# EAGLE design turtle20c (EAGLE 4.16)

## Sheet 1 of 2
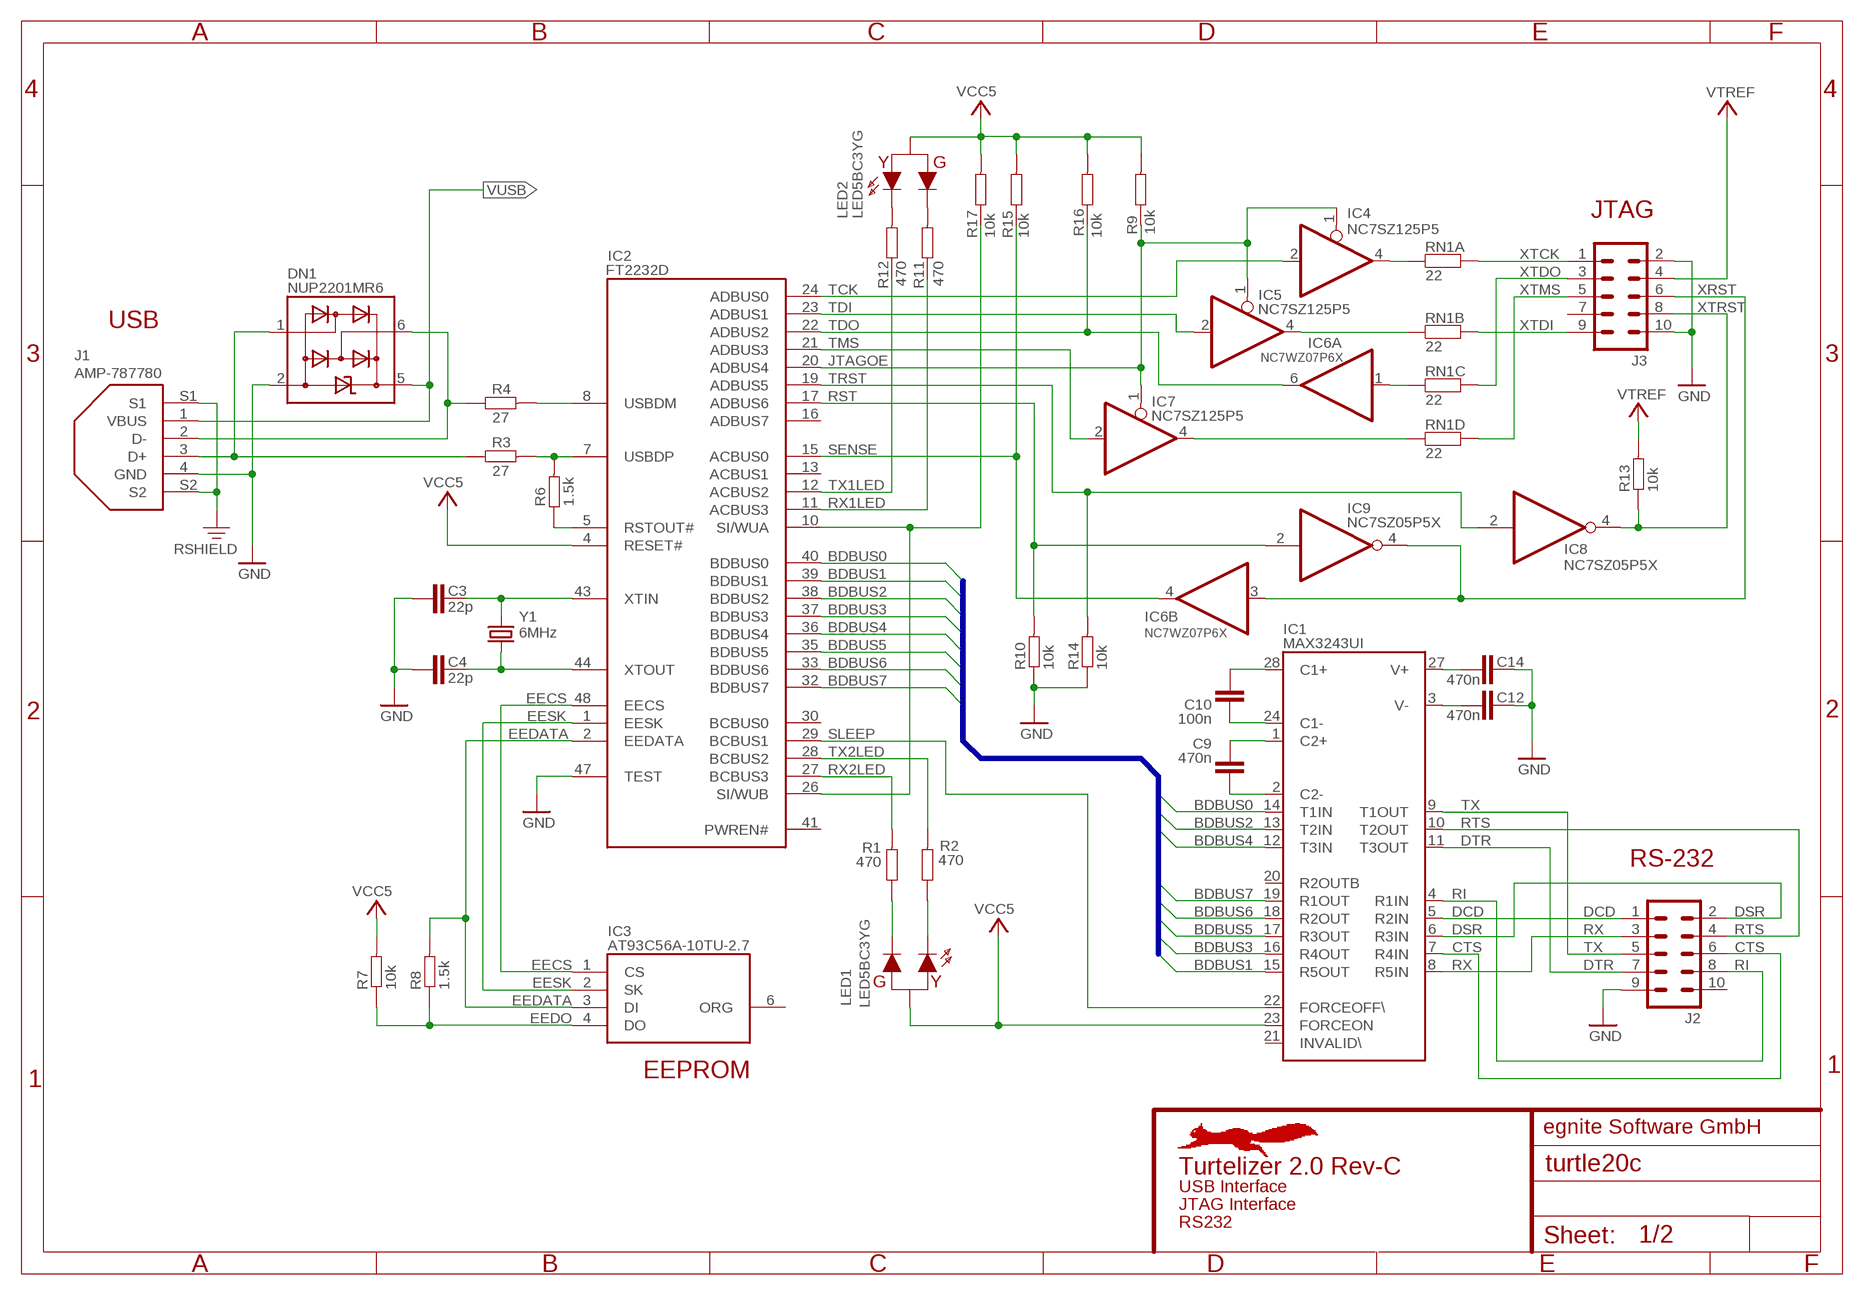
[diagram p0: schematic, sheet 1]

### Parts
C3  22p  C0402  [C0402]
C4  22p  C0402  [C0402]
C9  470n  C0603  [C0603]
C10  100n  C0603  [C0603]
C12  470n  C0603  [C0603]
C14  470n  C0603  [C0603]
DN1  NUP2201MR6  [TSSOP6]
IC1  MAX3243UI  [TSSOP28]
IC2  FT2232D  FT2232L  [LQFP-48]
IC3  AT93C56A-10TU-2.7  [TSSOP8]
IC4  NC7SZ125P5  [SOT353]
IC5  NC7SZ125P5  [SOT353]
IC6  NC7WZ07P6X  [SOT363]
IC7  NC7SZ125P5  [SOT353]
IC8  NC7SZ05P5X  [SOT353]
IC9  NC7SZ05P5X  [SOT353]
J1  AMP-787780  [AMP-787780]
J2  IDCCRIMP10  [IDCCRIMP10]
J3  IDCCRIMP10  [IDCCRIMP10]
LED1  LED5BC3YG  [LED3PIN]
LED2  LED5BC3YG  [LED3PIN]
R1  470  R0603  [R0603]
R2  470  R0603  [R0603]
R3  27  R0402  [R0402]
R4  27  R0402  [R0402]
R6  1.5k  R0402  [R0402]
R7  10k  R0402  [R0402]
R8  1.5k  R0402  [R0402]
R9  10k  R0402  [R0402]
R10  10k  R0402  [R0402]
R11  470  R0603  [R0603]
R12  470  R0603  [R0603]
R13  10k  R0402  [R0402]
R14  10k  R0402  [R0402]
R15  10k  R0402  [R0402]
R16  10k  R0402  [R0402]
R17  10k  R0402  [R0402]
RN1  22  CAY16  [CAY16]
Y1  6MHz  CRYSTALHC49SM  [HC49SM]

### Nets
BDBUS0: IC1.14(T1IN) IC2.40(BDBUS0)
BDBUS1: IC1.15(R5OUT) IC2.39(BDBUS1)
BDBUS2: IC1.13(T2IN) IC2.38(BDBUS2)
BDBUS3: IC1.16(R4OUT) IC2.37(BDBUS3)
BDBUS4: IC1.12(T3IN) IC2.36(BDBUS4)
BDBUS5: IC1.17(R3OUT) IC2.35(BDBUS5)
BDBUS6: IC1.18(R2OUT) IC2.33(BDBUS6)
BDBUS7: IC1.19(R1OUT) IC2.32(BDBUS7)
CTS: IC1.7(R4IN) J2.6
D+: DN1.1 J1.3(D+) R3.1
D-: DN1.6 J1.2(D-) R4.1
DCD: IC1.5(R2IN) J2.1
DSR: IC1.6(R3IN) J2.2
DTR: IC1.11(T3OUT) J2.7
EECS: IC2.48(EECS) IC3.1(CS)
EEDATA: IC2.2(EEDATA) IC3.3(DI) R8.2
EEDO: IC3.4(DO) R7.1 R8.1
EESK: IC2.1(EESK) IC3.2(SK)
GND: C3.2 C4.2 C12.2 C14.2 DN1.2 IC2.47(TEST) J1.4(GND) J2.9 J3.2 J3.10 R10.1 R14.1 ; also sheet 2
JTAGOE: IC2.20(ADBUS4) IC4.1(OE) IC5.1(OE) IC7.1(OE) R9.1
LCC1+: C10.2 IC1.28(C1+)
LCC1-: C10.1 IC1.24(C1-)
LCC2+: C9.2 IC1.1(C2+)
LCC2-: C9.1 IC1.2(C2-)
LCV+: C14.1 IC1.27(V+)
LCV-: C12.1 IC1.3(V-)
N$10: LED1.1(C1) R2.1
N$11: LED1.3(C2) R1.1
RI: IC1.4(R1IN) J2.8
RST: IC2.17(ADBUS6) IC9.2(I) R10.2
RSTOUT#: IC2.5(RSTOUT#) R6.1
RTS: IC1.10(T2OUT) J2.4
RX: IC1.8(R5IN) J2.3
RX1LED: IC2.11(ACBUS3) R11.1
RX1LR: LED2.3(C2) R11.2
RX2LED: IC2.27(BCBUS3) R1.2
SENSE: IC2.15(ACBUS0) IC6.4(B:O) R15.1
SHIELD: J1.S1 J1.S2 ; supply symbol labelled RSHIELD
SLEEP: IC1.22(FORCEOFF\) IC2.29(BCBUS1)
TCK: IC2.24(ADBUS0) IC4.2(I)
TDI: IC2.23(ADBUS1) IC5.2(I)
TDO: IC2.22(ADBUS2) IC6.6(A:O) R16.1
TMS: IC2.21(ADBUS3) IC7.2(I)
TRST: IC2.19(ADBUS5) IC8.2(I) R14.2
TTCK: IC4.4(O) RN1.1
TTDI: IC5.4(O) RN1.2
TTDO: IC6.1(A:I) RN1.3
TTMS: IC7.4(O) RN1.4
TX: IC1.9(T1OUT) J2.5
TX1LED: IC2.12(ACBUS2) R12.1
TX1LR: LED2.1(C1) R12.2
TX2LED: IC2.28(BCBUS2) R2.2
USBDM: IC2.8(USBDM) R4.2
USBDP: IC2.7(USBDP) R3.2 R6.2
VCC5: IC1.23(FORCEON) IC2.4(RESET#) LED1.2(A) LED2.2(A) R7.2 R9.2 R15.2 R16.2 R17.2 ; also sheet 2
VTREF: J3.4 R13.2 ; also sheet 2
VUSB: DN1.5 J1.1(VBUS) ; also sheet 2
WAKEUP#: IC2.10(SI/WUA) IC2.26(SI/WUB) R17.1
XRST: IC6.3(B:I) IC9.4(O) J3.6
XTCK: J3.1 RN1.8
XTDI: J3.9 RN1.7
XTDO: J3.3 RN1.6
XTIN: C3.1 IC2.43(XTIN) Y1.2
XTMS: J3.5 RN1.5
XTOUT: C4.1 IC2.44(XTOUT) Y1.1
XTRST: IC8.4(O) J3.8 R13.1
Unconnected: J2.10 J3.7

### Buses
BDBUS[0..7]

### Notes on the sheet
- JTAG
- USB
- RS-232
- EEPROM
- egnite Software GmbH
- Turtelizer 2.0 Rev-C
- USB Interface
- JTAG Interface
- RS232

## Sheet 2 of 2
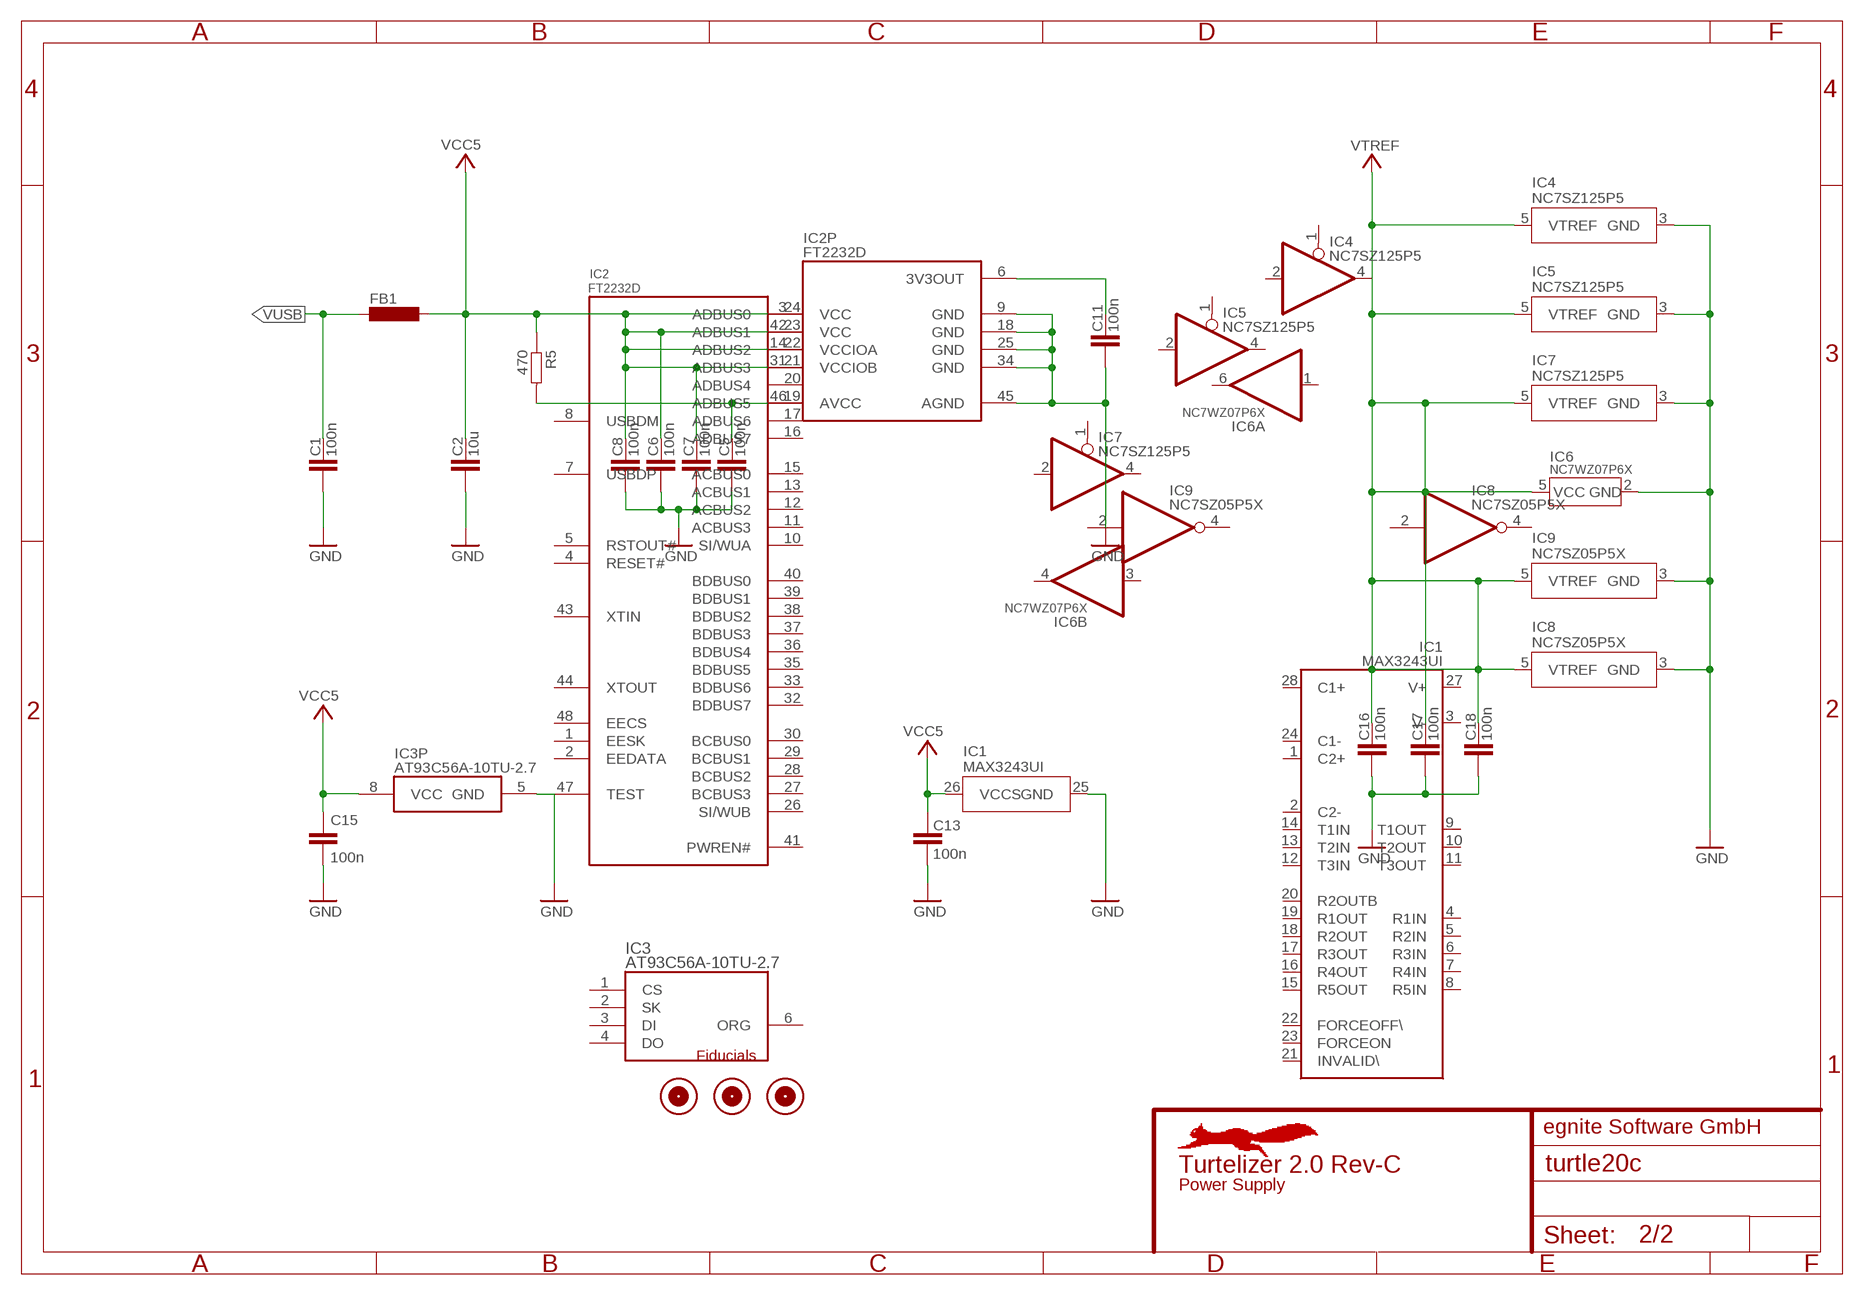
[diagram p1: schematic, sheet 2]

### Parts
C1  100n  C0603  [C0603]
C2  10u  C0805  [C0805]
C5  100n  C0603  [C0603]
C6  100n  C0603  [C0603]
C7  100n  C0603  [C0603]
C8  100n  C0603  [C0603]
C11  100n  C0603  [C0603]
C13  100n  C0603  [C0603]
C15  100n  C0603  [C0603]
C16  100n  C0603  [C0603]
C17  100n  C0603  [C0603]
C18  100n  C0603  [C0603]
FB1  BLM31A  [BLM31]
FM1  FIDUCIAL-1MM  [FIDUCIAL-1MM]
FM2  FIDUCIAL-1MM  [FIDUCIAL-1MM]
FM3  FIDUCIAL-1MM  [FIDUCIAL-1MM]
R5  470  R0603  [R0603]

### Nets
3V3CAP: C11.1 IC2.6(3V3OUT)
AVCC: C5.1 IC2.46(AVCC) R5.2
GND: C1.2 C2.2 C5.2 C6.2 C7.2 C8.2 C11.2 C13.2 C15.2 C16.2 C17.2 C18.2 IC1.25(GND) IC2.9(GND) IC2.18(GND) IC2.25(GND) IC2.34(GND) IC2.45(AGND) IC3.5(GND) IC4.3(GND) IC5.3(GND) IC6.2(P:GND) IC7.3(GND) IC8.3(GND) IC9.3(GND) ; also sheet 1
VCC5: C2.1 C6.1 C7.1 C8.1 C13.1 C15.1 FB1.1 IC1.26(VCCS) IC2.3(VCC) IC2.14(VCCIOA) IC2.31(VCCIOB) IC2.42(VCC) IC3.8(VCC) R5.1 ; also sheet 1
VTREF: C16.1 C17.1 C18.1 IC4.5(VTREF) IC5.5(VTREF) IC6.5(P:VCC3) IC7.5(VTREF) IC8.5(VTREF) IC9.5(VTREF) ; also sheet 1
VUSB: C1.1 FB1.2 ; also sheet 1
Unconnected: IC1.20(R2OUTB) IC1.21(INVALID\) IC2.13(ACBUS1) IC2.16(ADBUS7) IC2.30(BCBUS0) IC2.41(PWREN#) IC3.6(ORG)

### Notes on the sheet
- Fiducials
- egnite Software GmbH
- Turtelizer 2.0 Rev-C
- Power Supply

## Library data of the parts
C1-C18 = turtel20:C: Ceramic Chip Capacitor
DN1 = turtel20:NUP2201MR6
FB1 = turtel20:BLM31A: Murata Ferrite Bead
FM1-FM3 = turtel20:FIDUCIAL
IC1 = turtel20:MAX3243*: RS-232 Transceivers with AutoShutdown 1µA Supply-Current, True +3V to +5.5V http://dbserv.maxim-ic.com/
IC2 = turtel20:FT2232L
IC3 = turtel20:AT93C56A
IC4 IC5 IC7 = turtel20:NC7SZ125
IC6 = turtel20:NC7*07: TinyLogic Inverter - Open Drain Output WV High Speed: 0.9V-3.6V Supply, 3.6V tolerant, 1ns, 24mA Drive WZ Large V Range: 1.65V-5.5V Supply, 5V tolerant, 1.9ns, 24mA Drive
IC8 IC9 = turtel20:NC7SZ05
J1 = turtel20:AMP-787780
J2 J3 = turtel20:IDCCRIMP10: CONNECTOR
LED1 LED2 = turtelizerv1:LED5BC3YG
R1-R17 = turtel20:R: Chip Resistor
RN1 = turtel20:CAY16: Chip Resistor Array Multiple schematic symbols
Y1 = turtelizerv1:CRYSTAL: Crystal

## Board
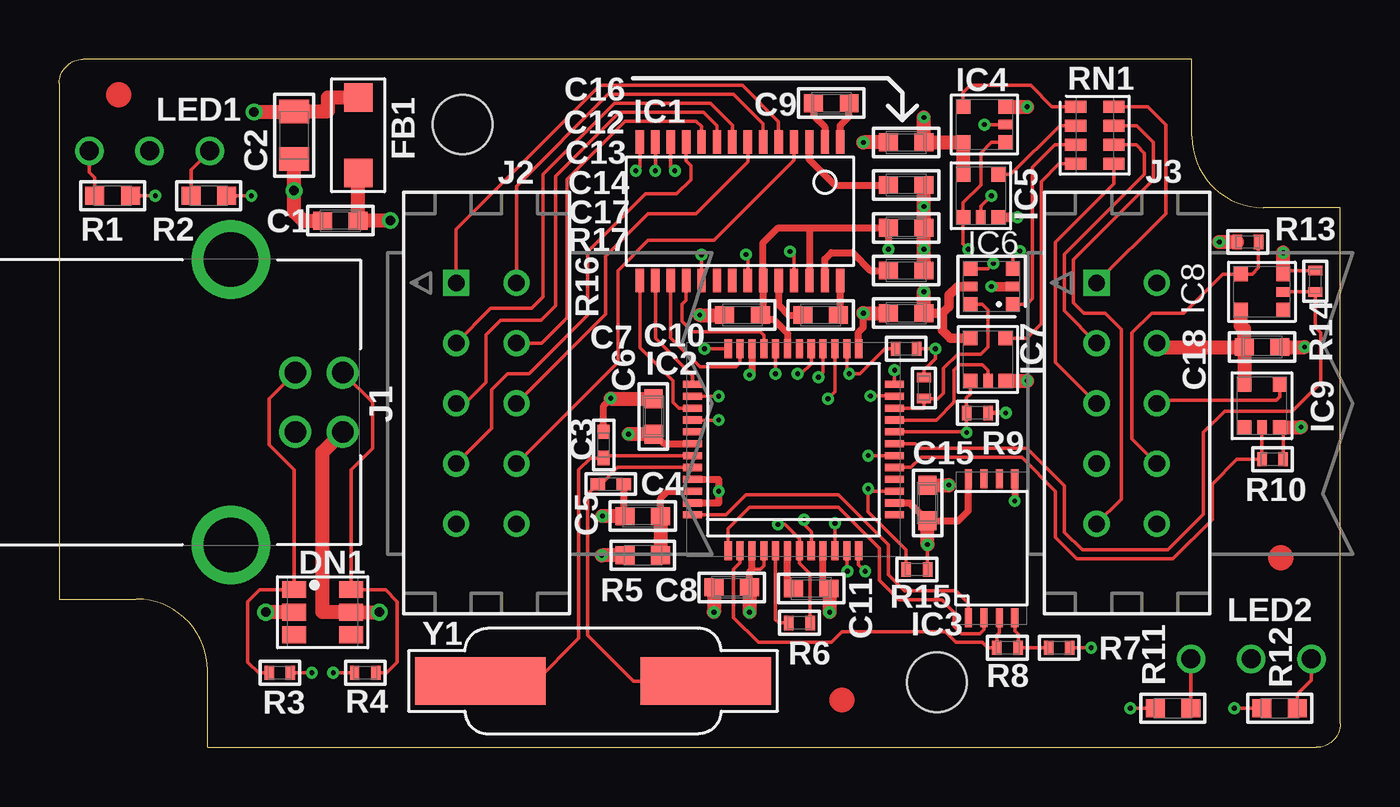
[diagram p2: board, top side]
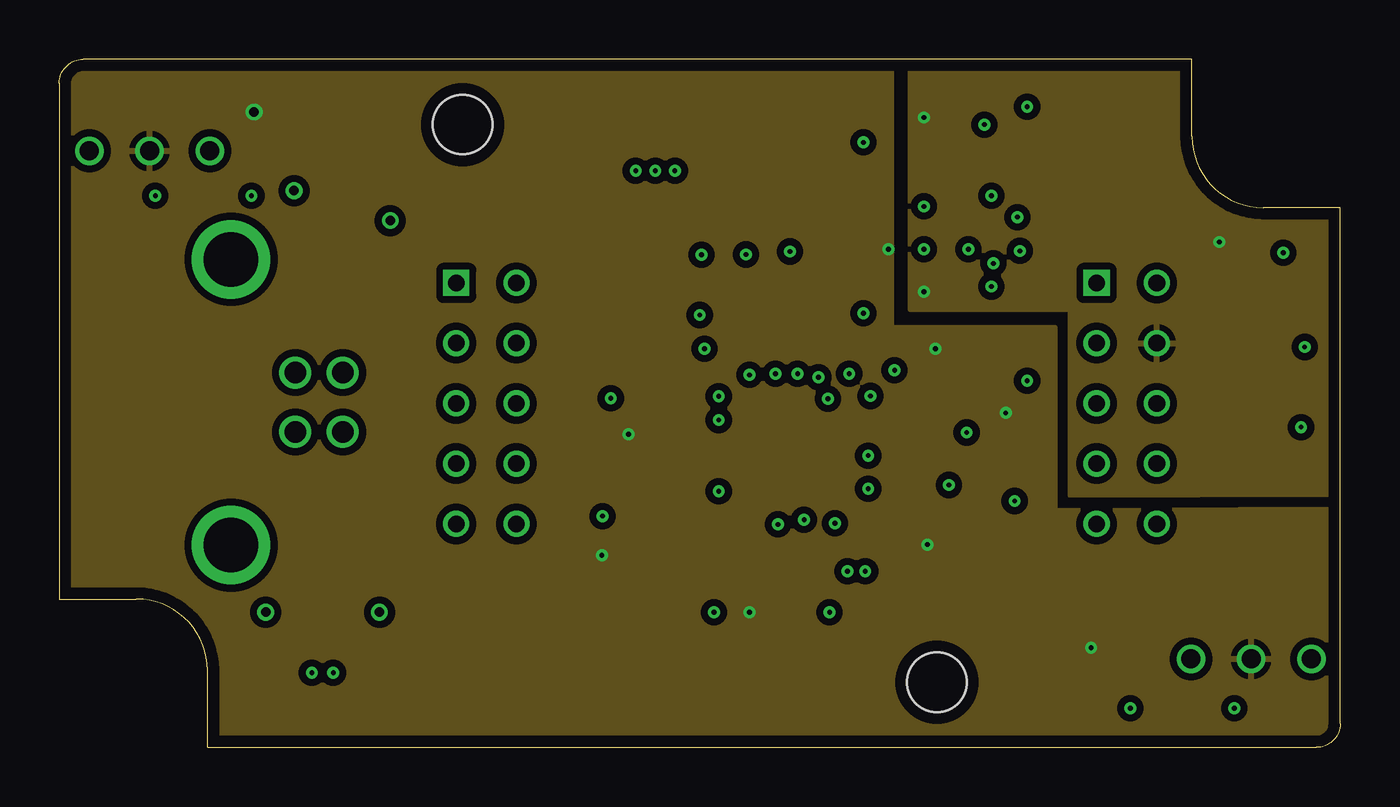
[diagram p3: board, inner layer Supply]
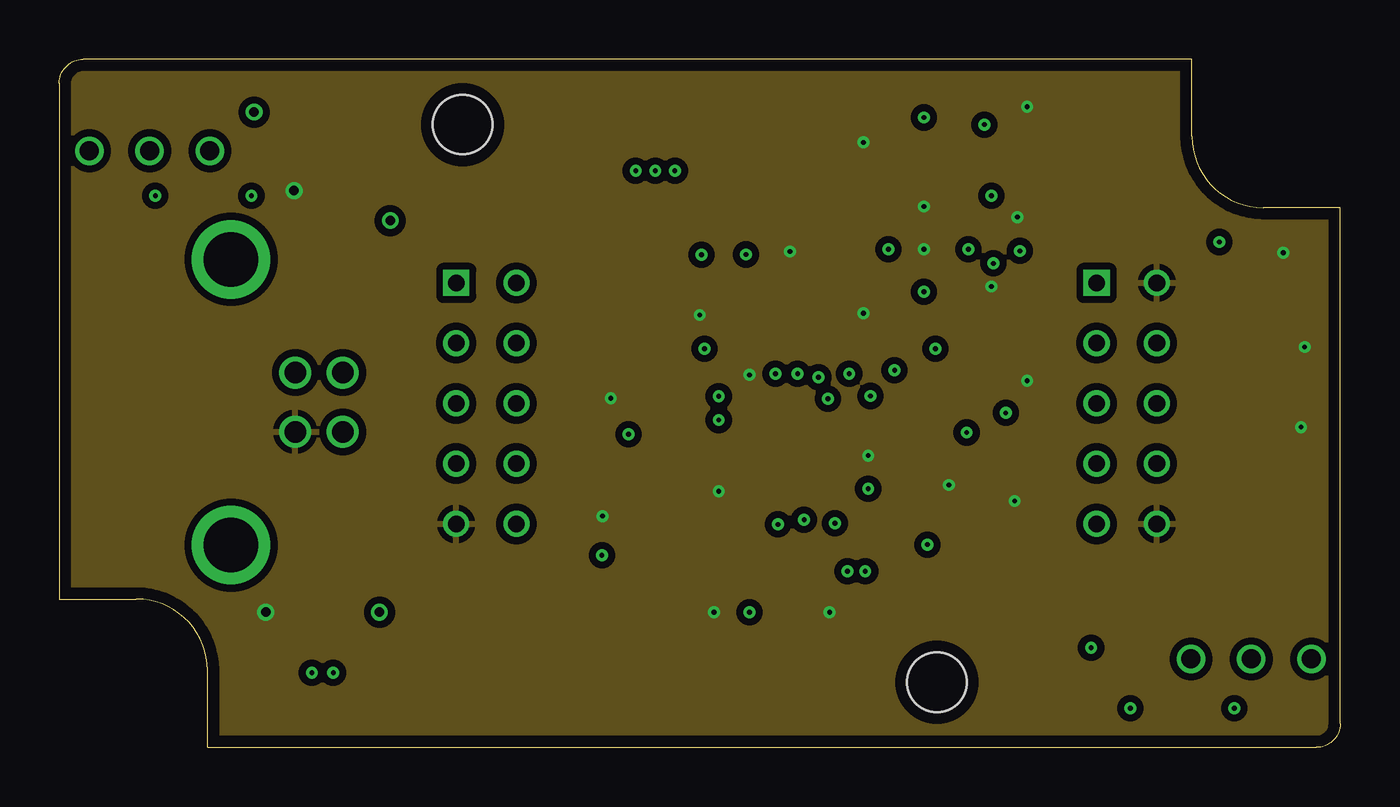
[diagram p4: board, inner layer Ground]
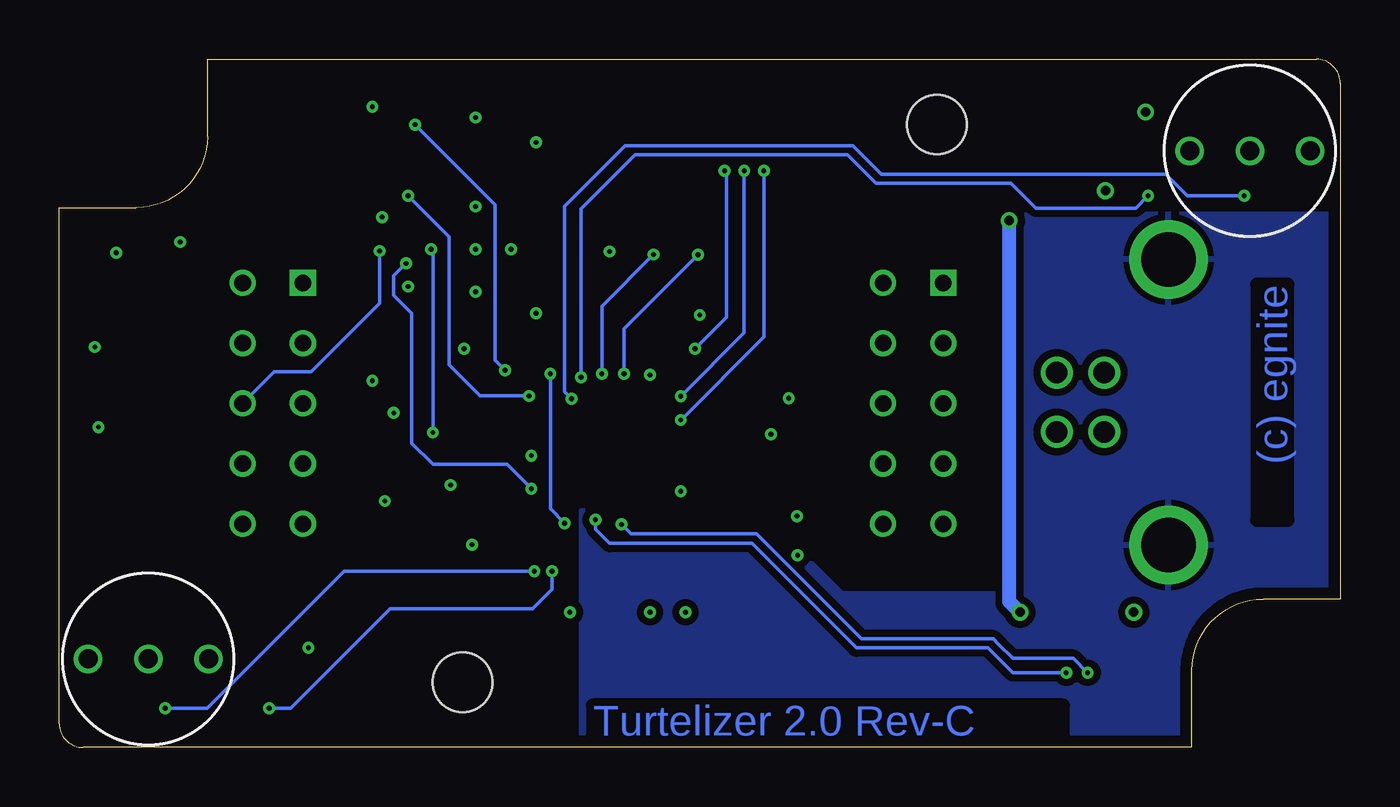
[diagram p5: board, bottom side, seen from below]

Size 54 x 29 mm. Coordinates in mm from the lower left corner, seen from the top.
Outline: 6.25,0 53,0 arc90 54,1 54,22.75 50.75,22.75 arc-90 47.75,25.75 47.75,29 1,29 arc90 0,28 0,6.25 3.25,6.25 arc-90 6.25,3.25 6.25,0
Copper layers (1*2+15*16): Top 0.035mm / dielectric 0.5mm / Supply 0.035mm / dielectric 0.5mm / Ground 0.035mm / dielectric 0.5mm / Bottom 0.035mm
Design rules "default": minimum track width 0.15mm, minimum drill 0.2mm, track to track 0.2mm, track to pad 0.2mm, pad to pad 0.2mm, via to via 0.2mm, smd to smd 0.2mm, copper to edge 0.5mm, drill to drill 0.5mm, minimum pad ring 0.2mm, minimum via ring 0.15mm, stop-mask expansion 0mil, vias tented up to drill 0.3mm, thermal gap 10mil
Holes 2.5 mm at 37,2.75 17,26.25

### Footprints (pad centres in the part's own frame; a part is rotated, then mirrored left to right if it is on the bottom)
C0603 = smd 0.8 x 0.75: 1 -0.75,0; 2 0.75,0
C0805 = smd 1 x 1.25: 1 -1,0; 2 1,0
C0402 = smd 0.6 x 0.5: 1 -0.55,0; 2 0.55,0
TSSOP6 = smd 0.7 x 1: 1 -0.95,-1.2; 2 0,-1.2; 3 0.95,-1.2; 4 0.95,1.2; 5 0,1.2; 6 -0.95,1.2
BLM31 = smd 1.2 x 1.2: 1 -1.6,0; 2 1.6,0
TSSOP28 = smd 0.35 x 1: 1 -4.225,-2.918; 2 -3.575,-2.918; 3 -2.925,-2.918; 4 -2.275,-2.918; 5 -1.625,-2.918; 6 -0.975,-2.918; 7 -0.325,-2.918; 8 0.325,-2.918; 9 0.975,-2.918; 10 1.625,-2.918; 11 2.275,-2.918; 12 2.925,-2.918; 13 3.575,-2.918; 14 4.225,-2.918; 15 4.225,2.918; 16 3.575,2.918; 17 2.925,2.918; 18 2.275,2.918; 19 1.625,2.918; 20 0.975,2.918; 21 0.325,2.918; 22 -0.325,2.918; 23 -0.975,2.918; 24 -1.625,2.918; 25 -2.275,2.918; 26 -2.925,2.918; 27 -3.575,2.918; 28 -4.225,2.918
LQFP-48 = smd 0.3 x 0.8: 1 -2.75,-4.25; 2 -2.25,-4.25; 3 -1.75,-4.25; 4 -1.25,-4.25; 5 -0.75,-4.25; 6 -0.25,-4.25; 7 0.25,-4.25; 8 0.75,-4.25; 9 1.25,-4.25; 10 1.75,-4.25; 11 2.25,-4.25; 12 2.75,-4.25; 25 2.75,4.25; 26 2.25,4.25; 27 1.75,4.25; 28 1.25,4.25; 29 0.75,4.25; 30 0.25,4.25; 31 -0.25,4.25; 32 -0.75,4.25; 33 -1.25,4.25; 34 -1.75,4.25; 35 -2.25,4.25; 36 -2.75,4.25 | smd 0.8 x 0.3: 13 4.25,-2.75; 14 4.25,-2.25; 15 4.25,-1.75; 16 4.25,-1.25; 17 4.25,-0.75; 18 4.25,-0.25; 19 4.25,0.25; 20 4.25,0.75; 21 4.25,1.25; 22 4.25,1.75; 23 4.25,2.25; 24 4.25,2.75; 37 -4.25,2.75; 38 -4.25,2.25; 39 -4.25,1.75; 40 -4.25,1.25; 41 -4.25,0.75; 42 -4.25,0.25; 43 -4.25,-0.25; 44 -4.25,-0.75; 45 -4.25,-1.25; 46 -4.25,-1.75; 47 -4.25,-2.25; 48 -4.25,-2.75
TSSOP8 = smd 0.3 x 0.8: 1 -0.975,-2.925; 2 -0.325,-2.925; 3 0.325,-2.925; 4 0.975,-2.925; 5 0.975,2.925; 6 0.325,2.925; 7 -0.325,2.925; 8 -0.975,2.925
SOT353 = smd 0.6 x 0.6: 1 -0.75,-0.9; 3 0.75,-0.9; 4 0.75,0.9; 5 -0.75,0.9 | smd 0.4 x 0.6: 2 0,-0.9
SOT363 = smd 0.6 x 0.6: 1 -0.75,-0.9; 3 0.75,-0.9; 4 0.75,0.9; 6 -0.75,0.9 | smd 0.4 x 0.6: 2 0,-0.9; 5 0,0.9
AMP-787780 = drill 0.9 round: 1 1.25,1; 2 -1.25,1; 3 -1.25,-1; 4 1.25,-1 | drill 2.3 round: S1 -6.02,-3.71; S2 6.02,-3.71
IDCCRIMP10 = drill 0.7 square: 1 -5.08,-1.27 | drill 0.7 round: 2 -5.08,1.27; 3 -2.54,-1.27; 4 -2.54,1.27; 5 0,-1.27; 6 0,1.27; 7 2.54,-1.27; 8 2.54,1.27; 9 5.08,-1.27; 10 5.08,1.27
LED3PIN = drill 0.8 round: 1 -2.54,0; 2 0,0; 3 2.54,0
R0603 = smd 0.8 x 0.75: 1 -0.75,0; 2 0.75,0
R0402 = smd 0.4 x 0.6: 1 -0.45,0; 2 0.45,0
CAY16 = smd 0.508 x 0.889: 1 -1.2,-0.805; 2 -0.4,-0.805; 3 0.4,-0.805; 4 1.2,-0.805; 5 1.2,0.805; 6 0.4,0.805; 7 -0.4,0.805; 8 -1.2,0.805
HC49SM = smd 5.5 x 2: 1 -4.75,0; 2 4.75,0

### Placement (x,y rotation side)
C1  11.85,22.2 180 top
C2  9.9,25.8 270 top
C3  22.95,12.75 90 top
C4  23.25,11.1 0 top
C5  24.6,9.75 180 top
C6  25.05,13.95 90 top
C7  28.8,18.23 180 top
C8  28.35,6.75 180 top
C9  32.55,27.15 0 top
C10  32.1,18.23 0 top
C11  31.7,6.7 0 top
C12  35.7,23.7 0 top
C13  35.7,21.9 0 top
C14  35.7,20.1 0 top
C15  36.6,10.3 90 top
C16  35.7,25.5 180 top
C17  35.7,18.3 180 top
C18  50.7,16.88 0 top
DN1  11.1,5.7 270 top
FB1  12.6,25.8 270 top
FM1  2.5,27.5 0 top
FM2  33,2 0 top
FM3  51.5,8 0 top
IC1  28.7,22.6 180 top
IC2  30.95,12.55 0 top
IC3  39.3,8.4 0 top
IC4  39,26.25 90 top
IC5  38.85,23.25 0 top
IC6  39.3,19.43 90 top
IC7  39.15,16.35 0 top
IC8  50.7,19.2 90 top
IC9  50.7,14.4 0 top
J1  10.95,14.55 270 top
J2  18,14.5 270 top
J3  45,14.5 270 top
LED1  3.81,25.15 0 bottom
LED2  50.25,3.73 0 bottom
R1  2.25,23.25 0 top
R2  6.3,23.25 0 top
R3  9.3,3.15 0 top
R4  12.9,3.15 180 top
R5  24.6,8.1 0 top
R6  31.2,5.25 0 top
R7  42.15,4.2 0 top
R8  39.98,4.2 180 top
R9  38.7,14.1 0 top
R10  51.15,12.15 180 top
R11  46.95,1.65 0 top
R12  51.45,1.65 0 top
R13  50.1,21.3 180 top
R14  52.95,19.65 270 top
R15  36.15,7.5 0 top
R16  36.45,15.15 90 top
R17  35.7,16.8 0 top
RN1  43.65,25.8 270 top
Y1  22.5,2.8 180 top

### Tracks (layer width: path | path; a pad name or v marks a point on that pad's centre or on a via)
3V3CAP
  Top 0.3: IC2.6 30.7,6.95 C11.1
AVCC
  Top 0.3: IC2.46 25.65,10.8 25.35,10.5 C5.1
  Top 0.6: C5.1 R5.2
BDBUS0  (via drill 0.2)
  Top 0.15: IC2.40 v27.8,13.8 | IC1.14 24.48,24.48 v24.3,24.3
  Bottom 0.15: v27.8,13.8 24.3,17.3 v24.3,24.3
BDBUS1
  Top 0.15: IC1.15 24.48,16.85 25.88,15.45 25.88,14.55 26.12,14.3 IC2.39
BDBUS2  (via drill 0.2)
  Top 0.15: IC2.38 v27.8,14.8 | v25.12,24.3 IC1.13
  Bottom 0.15: v27.8,14.8 25.12,17.48 v25.12,24.3
BDBUS3
  Top 0.15: IC1.16 25.12,17.25 26.7,15.68 IC2.37
BDBUS4  (via drill 0.2)
  Top 0.15: v27.2,16.8 IC2.36 | IC1.12 25.77,24.48 v25.95,24.3
  Bottom 0.15: v27.2,16.8 25.88,18.12 25.88,24.23 v25.95,24.3
BDBUS5
  Top 0.15: IC1.17 25.77,17.27 27,16.05 28.54,16.05 28.7,16.21 IC2.35
BDBUS6
  Top 0.15: IC1.18 26.43,18.85 26.25,18.68 26.25,17.96 26.7,17.51 29.55,17.51 29.7,17.36 IC2.33
BDBUS7  (via drill 0.2)
  Top 0.15: IC2.32 30.2,15.76 v30.19,15.75 | 27.07,20.77 v27.07,20.76 IC1.19
  Bottom 0.15: v27.07,20.76 30.19,17.65 v30.19,15.75
CTS
  Top 0.15: J2.6 23.02,18.25 23.02,20.7 24.82,22.5 26.85,22.5 29.02,24.68 IC1.7
D+
  Top 0.15: J1.3 8.85,14.7 8.85,12.75 9.9,11.7 DN1.1 8.45,6.65 7.95,6.15 7.95,3.6 8.4,3.15 R3.1
D-
  Top 0.15: R4.1 13.8,3.15 14.25,3.6 14.25,6.15 13.75,6.65 DN1.6 12.3,11.7 13.2,12.6 13.2,14.55 J1.2
DCD
  Top 0.15: IC1.5 30.32,26.38 28.8,27.9 22.8,27.9 16.73,21.83 J2.1
DSR
  Top 0.15: IC1.6 29.68,26.27 28.43,27.52 23.14,27.52 19.27,23.66 J2.2
DTR
  Top 0.15: J2.7 18.23,13.46 18.23,15.07 18.9,15.75 19.8,15.75 22.27,18.23 22.27,20.85 22.26,20.87 24.71,23.32 26.02,23.32 26.62,23.93 26.62,24.52 26.43,24.73 IC1.11
EECS
  Top 0.15: IC3.1 38.33,6.08 37.8,6.6 35.62,6.6 34.95,7.28 34.95,8.55 32.85,10.65 28.95,10.65 28.1,9.8 IC2.48
EEDATA
  Top 0.15: IC3.3 39.62,4.83 39.52,4.72 R8.2 39.15,4.2 38.92,4.42 37.8,4.42 37.35,4.88 33,4.88 32.55,4.42 29.48,4.42 28.43,5.47 28.43,7.28 28.43,7.5 28.7,7.78 IC2.2
EEDO
  Top 0.15: IC3.4 40.27,4.91 40.42,4.76 R8.1 R7.1
EESK
  Top 0.15: IC3.2 38.98,4.96 38.81,4.8 38.02,4.8 37.73,5.1 37.73,5.7 37.2,6.22 35.4,6.22 34.58,7.05 34.58,8.4 32.85,10.12 29.55,10.12 29.1,10.12 28.2,9.22 IC2.1
GND  (via drill 0.2, 0.4)
  Top 0.15: IC2.18 v34.1,12.3 | IC1.25 30.98,20.73 v30.8,20.9 | R14.1 51.75,20.1 IC8.3 | R10.1 51.6,13.35 IC9.3
  Top 0.3: IC2.45 27.8,11.3 v27.8,10.8 27.8,10.3 IC2.47 | IC2.34 29.2,15.8 v29.1,15.7 | IC2.25 33.7,17.5 33.9,17.7 v33.9,18.3 | IC3.5 v40.27,10.39 | C4.2 23.8,9.8 C5.2 | C3.2 22.95,14.4 v23.25,14.7 | IC2.9 32.2,6.95 C11.2
  Top 0.4: IC6.2 v39.3,19.43 | IC5.3 v40.39,22.35
  Top 0.6: C5.2 v22.9,9.75 | v27,18.23 C7.2 | DN1.2 v8.7,5.7 | C2.2 v9.9,23.46 9.9,22.57 10.28,22.2 C1.2 | IC4.3 v40.8,27 | C16.2 v33.9,25.5 | C12.2 v36.45,22.8 C13.2 v36.45,21 C14.2 | v33.9,18.3 C17.2 | C15.2 37.49,11.05 v37.5,11.06 | IC7.3 v40.8,15.45 | IC8.3 v51.6,20.85 | IC9.3 v52.35,13.5 | C18.2 v52.5,16.88 | v23.25,14.71 v23.25,14.7 C6.2 | C8.2 v27.6,5.7 | C11.2 32.48,6.67 v32.48,5.7
  pour Ground (isolate 0.3): 0.5,28.5 53.5,28.5 53.5,0.5 0.4,0.5
JTAGOE  (via drill 0.2)
  Top 0.15: IC7.1 38.4,14.89 38.25,14.74 R9.1 v38.25,13.28 38.23,13.3 IC2.20 | IC4.1 39.3,25.5 38.85,25.05 38.85,23.7 38.1,22.95 IC5.1 38.1,21.23 v38.33,21
  Bottom 0.15: v38.25,13.28 38.25,20.93 v38.33,21
LCC1+
  Top 0.3: C10.2 32.85,18.26 32.92,18.34 IC1.28
LCC1-
  Top 0.3: IC1.24 30.32,18.65 30.75,18.23 C10.1
LCC2+
  Top 0.3: IC1.1 32.92,26.21 33.3,26.59 C9.2
LCC2-
  Top 0.3: IC1.2 32.27,26.15 31.8,26.62 C9.1
LCV+
  Top 0.3: IC1.27 32.27,20.57 32.55,20.85 33.45,20.85 34.2,20.1 C14.1
LCV-
  Top 0.3: IC1.3 31.62,24.77 32.7,23.7 C12.1
N$10
  Top 0.15: LED1.1 5.55,24.35 R2.1
N$11
  Top 0.15: LED1.3 1.27,24.23 1.5,24 R1.1
RI
  Top 0.15: J2.8 23.55,16.24 23.55,20.1 24.82,21.38 27.6,21.38 30.98,24.75 IC1.4
RST
  Top 0.15: IC2.17 35.91,11.8 36.34,12.22 40.58,12.22 42,10.8 42,8.85 42.9,7.95 46.95,7.95 48.6,9.6 48.6,11.1 49.65,12.15 R10.2 IC9.2
RSTOUT#
  Top 0.15: R6.1 30.34,5.25 30.2,5.39 IC2.5
RTS
  Top 0.15: J2.4 20.34,17.04 21.4,18.1 21.4,23.95 23.85,26.4 26.85,26.4 27.07,26.18 IC1.10
RX
  Top 0.15: J2.3 18.19,18.5 19.9,18.5 20.4,19 20.4,24.15 23.4,27.15 27.45,27.15 28.38,26.23 IC1.8
RX1LED  (via drill 0.2)
  Top 0.15: IC2.11 33.2,7.45 v33.23,7.42 | v45.15,1.65 R11.1
  Bottom 0.15: v33.23,7.42 33.23,6.67 34.05,5.85 40.05,5.85 44.25,1.65 v45.15,1.65
RX1LR
  Top 0.15: LED2.3 47.71,3.57 47.7,3.56 R11.2
RX2LED  (via drill 0.2)
  Top 0.15: IC2.27 32.7,15 v32.4,14.7 | R1.2 v4.05,23.25
  Bottom 0.15: v32.4,14.7 32.7,15 32.7,22.8 30.15,25.35 20.55,25.35 19.35,24.15 7.35,24.15 6.45,23.25 v4.05,23.25
SENSE  (via drill 0.2)
  Top 0.15: IC2.15 34.2,10.8 v34.1,10.9 34.09,10.91 34.09,9.94 35.7,8.32 R15.1 | IC6.4 39.15,20.18 v39.38,20.4
  Bottom 0.15: v34.1,10.9 35.12,11.93 38.25,11.93 39.15,12.82 39.15,18.3 39.9,19.05 39.9,19.88 v39.38,20.4
SHIELD
  pour Bottom (isolate 0.3): 0.5,22.5 14,22.5 14,6.5 21,6.5 24.5,10 32,10 32,0.5 0.5,0.5
SLEEP  (via drill 0.2)
  Top 0.15: IC1.22 29.02,20.7 v28.95,20.77 | v31.12,15.75 31.27,15.75 31.7,16.18 IC2.29
  Bottom 0.15: v28.95,20.77 31.12,18.6 v31.12,15.75
TCK  (via drill 0.2)
  Top 0.15: IC2.24 35.21,15.31 v35.21,15.9 | v39,26.25 IC4.2
  Bottom 0.15: v39,26.25 35.62,22.88 35.62,16.31 v35.21,15.9
TDI  (via drill 0.2)
  Top 0.15: IC2.23 35.19,14.81 v34.2,14.81 | IC5.2 38.85,22.8 v39.3,23.25
  Bottom 0.15: v34.2,14.81 36.26,14.81 37.58,16.12 37.58,21.52 v39.3,23.25
TDO
  Top 0.15: IC2.22 36.45,14.3 R16.1 37.05,14.7 37.27,14.93 37.27,15.97 37.88,16.57 38.85,16.57 39.15,16.88 39.15,18.45 38.92,18.68 IC6.6
TMS
  Top 0.15: IC2.21 36.98,13.8 37.73,14.55 37.73,15.9 37.95,16.12 38.92,16.12 39.15,15.9 IC7.2
TRST
  Top 0.15: IC2.19 36.1,12.8 36.3,12.6 40.8,12.6 42.38,11.03 42.38,9.07 43.12,8.32 46.73,8.32 48.23,9.82 48.23,13.28 49.12,14.18 51.98,14.18 53.17,15.38 53.17,17.48 52.95,17.7 R14.2 IC8.2
TTCK
  Top 0.15: IC4.4 38.1,27.6 38.4,27.9 40.95,27.9 41.85,27 RN1.1
TTDI
  Top 0.15: RN1.2 42.17,26.2 40.12,24.15 IC5.4
TTDO
  Top 0.15: RN1.3 41.98,25.4 41.02,24.45 41.02,18.9 40.8,18.68 IC6.1
TTMS
  Top 0.15: IC7.4 40.8,17.25 41.4,17.85 41.4,23.85 42.15,24.6 RN1.4
TX
  Top 0.15: J2.5 17.1,14.5 18,15.4 18,17.4 18.6,18 20.3,18 20.93,18.62 20.93,24.07 21.23,24.38 23.62,26.77 27.15,26.77 27.73,26.2 IC1.9
TX1LED  (via drill 0.2)
  Top 0.15: IC2.12 33.7,7.7 v33.98,7.42 | v49.54,1.65 R12.1
  Bottom 0.15: v33.98,7.42 42,7.42 47.77,1.65 v49.54,1.65
TX1LR
  Top 0.15: LED2.1 52.79,2.84 52.2,2.25 R12.2
TX2LED  (via drill 0.2)
  Top 0.15: IC2.28 32.2,15.8 v32,15.6 | R2.2 v8.1,23.25
  Bottom 0.15: v32,15.6 32,22.7 29.73,24.98 20.77,24.98 19.57,23.77 13.88,23.77 12.82,22.73 8.62,22.73 v8.1,23.25
USBDM  (via drill 0.2)
  Top 0.15: v31.4,9.6 31.4,9.4 31.7,9.1 IC2.8 | R4.2 v11.55,3.15
  Bottom 0.15: v31.4,9.6 31.4,9.2 30.8,8.6 24.8,8.6 20.4,4.2 14.85,4.2 13.8,3.15 v11.55,3.15
USBDP  (via drill 0.2)
  Top 0.15: v30.3,9.4 30.6,9.4 31.2,8.8 IC2.7 31.2,7.76 31.65,7.31 R6.2 | R3.2 v10.65,3.15
  Bottom 0.15: v30.3,9.4 29.9,9 24.6,9 20.18,4.58 14.62,4.58 14.4,4.35 13.8,3.75 11.25,3.75 v10.65,3.15
VCC5  (via drill 0.2, 0.4)
  Top 0.15: R17.2 v36.94,16.8 36.94,16.39 36.45,15.9 R16.2 | R7.2 v43.5,4.2 | R15.2 v36.6,8.55 | 29.2,7.5 29.55,7.5 29.7,7.65 IC2.4
  Top 0.2: 31.6,20 31.62,19.98 IC1.26 | R9.2 v39.9,14.1
  Top 0.3: C6.1 25.1,13.2 25.5,12.8 IC2.42 | IC2.3 29.2,7.5 29.1,7.4 C8.1 | 31.69,21.9 C13.1 v34.95,21 | IC3.8 38.33,9.97 37.9,9.55 C15.1 36.6,9.56 35.86,10.3 IC2.14 | IC2.31 30.7,17.45 30.11,18.04 29.74,18.04 C7.1 29.55,18.3 29.68,18.43 IC1.23 29.68,21.27 30.3,21.9 31.69,21.9 | IC1.26 31.62,21.84 31.69,21.9
  Top 0.6: v36.6,8.55 C15.1 | FB1.1 11.32,27.4 11.32,26.81 10.05,26.81 10.05,26.8 C2.1 9.88,26.77 v8.21,26.77 | R5.1 v22.88,8.1 | C8.1 v29.1,5.7 | C6.1 v24,13.2
  pour Supply (isolate 0.3): 0.3,28.5 35.1,28.5 35.1,17.7 42,17.7 42,10 53.55,10.05 53.55,0.45 0.3,0.45
VTREF  (via drill 0.2)
  Top 0.4: 37.24,18.3 C17.1 | 37.24,18.3 37.5,18.56 37.5,19.05 37.88,19.43 IC6.5 | IC7.5 37.58,17.25 37.24,17.59 37.24,18.3
  Top 0.6: C17.1 v36.45,19.2 | IC8.5 49.8,17.77 49.95,17.62 C18.1 | C18.1 IC9.5 | J3.4 46.42,16.88 C18.1 | v36.45,26.55 C16.1 IC4.5 IC5.5 | R13.2 v48.9,21.3
  pour Supply (isolate 0.3): 35.85,28.5 53.5,28.5 53.55,10.65 42.6,10.6 42.6,18.45 35.85,18.45
VUSB  (via drill 0.4)
  Top 0.6: J1.1 11.1,12.45 11.1,5.7 DN1.5 v13.5,5.7 | 13.99,22.2 v13.95,22.2 C1.1 FB1.2
  Bottom 0.6: v13.5,5.7 13.95,6.15 v13.95,22.2
WAKEUP#  (via drill 0.2)
  Top 0.15: IC2.10 v32.7,9.45 | R17.1 34.8,16.8 33.75,15.75 v33.3,15.75 33.2,15.85 IC2.26
  Bottom 0.15: v32.7,9.45 33.3,10.05 v33.3,15.75
XRST  (via drill 0.2)
  Top 0.15: J3.6 46.4,14.62 51.3,14.62 51.45,14.78 IC9.4 | IC6.3 40.2,20.62 v40.5,20.93
  Bottom 0.15: J3.6 44.95,15.82 43.39,15.82 40.5,18.71 v40.5,20.93
XTCK
  Top 0.15: J3.1 46.65,22.5 46.65,26.25 45.9,27 RN1.8
XTDI
  Top 0.15: RN1.7 45.42,26.2 46.12,25.5 46.12,23.93 42.75,20.55 42.75,18.75 43.2,18.3 44.1,18.3 44.77,17.62 44.77,10.46 J3.9
XTDO
  Top 0.15: RN1.6 45.4,25.4 45.75,25.05 45.75,24.15 42.38,20.77 42.38,18.39 J3.3
XTIN
  Top 0.15: Y1.2 20.1,2.8 21.9,4.6 21.9,11.7 22.39,12.19 22.95,12.19 | 22.95,12.19 C3.1 | IC2.43 23.06,12.3 22.95,12.19
XTMS
  Top 0.15: J3.5 42,16.23 42,21.3 44.45,23.75 RN1.5
XTOUT
  Top 0.15: Y1.1 24.2,2.8 22.27,4.72 22.27,10.68 C4.1 | C4.1 22.76,11.1 | C4.1 22.84,11.1 23.54,11.8 IC2.44
XTRST
  Top 0.15: J3.8 45.23,13.01 45.23,17.48 46.05,18.3 47.4,18.3 49.05,19.95 IC8.4 50.29,19.95 50.55,20.21 R13.1

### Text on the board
Bottom: (c) egnite | Turtelizer 2.0 Rev-C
